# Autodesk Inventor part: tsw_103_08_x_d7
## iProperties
Created: 2006-03
Part Number: tsw_103_08_x_d7
Document SubType Name: Modeling
Designer: Elise Moss
Author: Elise Moss
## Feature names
1. Base1
